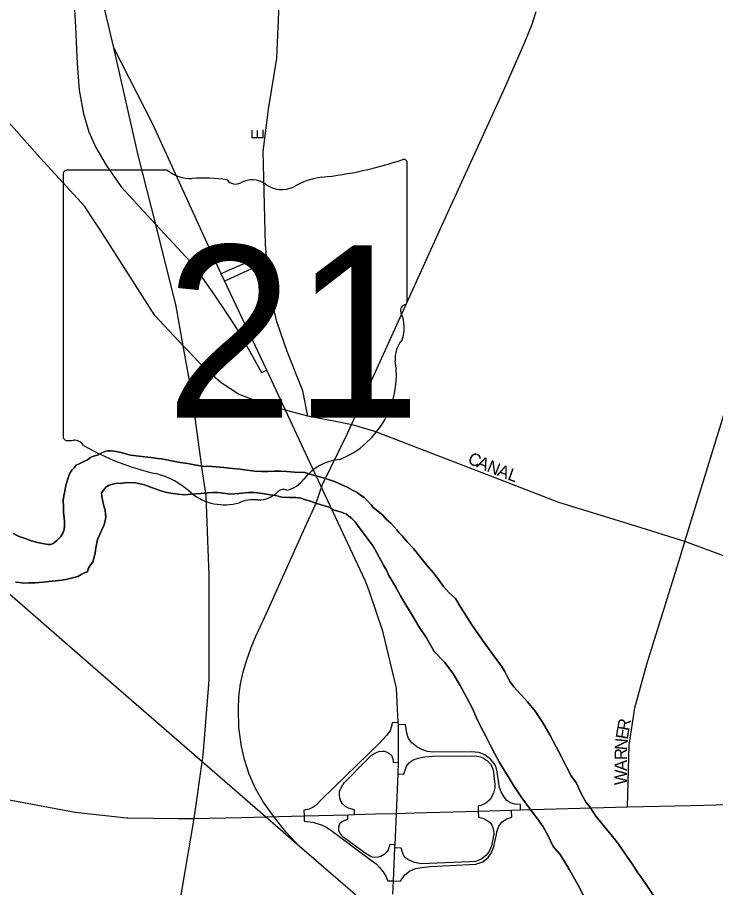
# Model space of a CAD drawing. Extents: x -561 to 1170, y 0 to 846.
# Drawn here: x 278.05 to 285.68, y 204.45 to 213.95 of the extents above; entities that cross this region are included whole.
import ezdxf

# ---------------------------------------------------------------- set-up
doc = ezdxf.new("R2010")
doc.units = 0
for name, color, linetype in [('GM_X_City_Street', 7, 'Continuous'), ('GM_X_City_Street_Text', 7, 'Continuous'), ('GM_X_Interchange_Ramps', 7, 'Continuous'), ('GM_X_Interstate_Route', 7, 'Continuous'), ('GM_X_Major_River', 7, 'Continuous'), ('GM_X_Rail_Line', 7, 'Continuous'), ('GM_X_State_Location', 7, 'Continuous'), ('GM_X_State_Route', 7, 'Continuous'), ('GM_X_State_Shield', 7, 'Continuous')]:
    doc.layers.add(name, color=color, linetype=linetype)

msp = doc.modelspace()

# ---------------------------------------------------------------- linework, layer by layer
at = {"layer": 'GM_X_City_Street'}
for points in [[(280.775, 212.772), (280.7968, 212.9466), (280.8872, 213.5039), (280.9956, 215.9266), (281.0778, 220.8309), (281.1272, 223.8527), (281.2011, 224.3427), (281.5216, 225.8717), (282.3892, 230.0692)], [(285.2926, 208.0563), (285.3457, 208.2277), (286.2713, 211.2389), (286.6055, 212.1521), (286.7989, 212.696), (287.0223, 213.4263), (287.3816, 214.3895), (287.5383, 214.9609), (287.6351, 215.4309), (287.718, 215.9424), (287.739, 216.3547), (287.7421, 216.509), (287.7345, 216.8917), (287.697, 217.6347), (287.5789, 219.1858), (287.5227, 220.4689), (287.5339, 220.8628), (287.5677, 221.1667), (287.6352, 221.5945), (287.8013, 222.1355), (287.8714, 222.4776), (288.0388, 222.7552), (288.458, 223.4643)], [(278.8652, 211.7732), (278.7929, 211.8839), (278.3049, 212.4159), (277.7013, 213.088), (277.4183, 213.3564), (277.0816, 213.5419), (276.7449, 213.6542), (276.4034, 213.6737), (276.0389, 213.6298), (273.3908, 213.1026), (272.0753, 212.8342), (271.6703, 212.7953), (271.385, 212.8644)], [(281.2268, 209.5946), (281.1707, 209.8734), (281.0023, 210.3008), (280.8913, 210.6173), (280.8092, 210.9502), (280.7814, 211.2676), (280.7746, 211.3458), (280.7639, 211.4681), (280.7393, 212.4862), (280.775, 212.772)], [(279.9088, 210.319), (279.8658, 210.3648), (279.5566, 210.6941), (278.9588, 211.6301), (278.8652, 211.7732)], [(281.2268, 209.5946), (280.9846, 209.6601), (280.7791, 209.7158), (280.4679, 209.8364), (280.2806, 209.9604), (280.0964, 210.1192), (279.9088, 210.319)], [(281.6913, 209.5033), (281.5095, 209.5402), (281.2268, 209.5946)], [(283.3187, 208.9034), (281.9589, 209.429), (281.7525, 209.491), (281.6913, 209.5033)], [(284.8106, 208.3926), (283.9695, 208.6518), (283.3187, 208.9034)], [(287.7327, 206.4817), (287.4077, 206.9503), (287.1265, 207.3345), (286.9481, 207.5404), (286.7609, 207.6708), (286.5209, 207.7942), (286.1985, 207.9108), (285.3457, 208.2277), (284.8106, 208.3926)], [(284.7195, 205.3284), (284.7374, 206.002), (284.7973, 206.4096), (284.9311, 206.8879), (285.2926, 208.0563)]]:
    msp.add_lwpolyline(points, dxfattribs=at)
at = {"layer": 'GM_X_Interchange_Ramps'}
for points in [[(278.5779, 215.858), (278.4451, 215.8246), (278.533, 215.3781), (278.584, 215.078), (278.6361, 214.6461), (278.668, 214.2397), (278.6908, 213.8431), (278.7078, 213.4448), (278.7304, 213.1553), (278.775, 212.8977), (278.8333, 212.7007), (278.9097, 212.5278), (279.0235, 212.3347), (279.1876, 212.0997), (279.3923, 211.8767), (279.5649, 211.6893), (279.9399, 211.2825), (280.0643, 211.1176), (280.1829, 210.9511), (280.3521, 210.6987), (280.4557, 210.5403), (280.6092, 210.2769), (280.7208, 210.0705), (280.7807, 210.0967)], [(280.7746, 211.3458), (280.7069, 211.3332), (280.3434, 211.1782), (280.279, 211.1499)], [(280.3158, 211.0728), (280.3771, 211.0996), (280.7157, 211.2554), (280.7814, 211.2676)], [(282.214, 206.2516), (282.149, 206.2476), (282.1415, 206.207), (282.125, 206.1597), (282.0853, 206.1081), (282.0178, 206.0327), (281.3749, 205.4094), (281.3184, 205.3495), (281.2838, 205.3248), (281.2404, 205.3051), (281.1845, 205.2944), (281.1851, 205.232)], [(283.5511, 205.2959), (283.5496, 205.3539), (283.4913, 205.3578), (283.4375, 205.373), (283.4008, 205.4006), (283.375, 205.4333), (283.3393, 205.4928), (283.322, 205.542), (283.3115, 205.5841), (283.3113, 205.587), (283.2951, 205.7134), (283.2888, 205.7441), (283.279, 205.773), (283.2639, 205.8025), (283.2202, 205.854), (283.1634, 205.8941), (283.1263, 205.9121), (283.0933, 205.9215), (283.0139, 205.9295), (282.5913, 205.9286), (282.535, 205.935), (282.4776, 205.9537), (282.4169, 205.9857), (282.3629, 206.0287), (282.3265, 206.0773), (282.3066, 206.1358), (282.2939, 206.2299), (282.2155, 206.2239)], [(281.7371, 205.2463), (281.7361, 205.2983), (281.6726, 205.3142), (281.6374, 205.3339), (281.6051, 205.3618), (281.5883, 205.3929), (281.5774, 205.4253), (281.573, 205.4628), (281.5734, 205.4968), (281.5932, 205.5444), (281.6289, 205.596), (281.8597, 205.8321), (281.9226, 205.8937), (281.9583, 205.9175), (282.0019, 205.9334), (282.0416, 205.9374), (282.0694, 205.9374), (282.1131, 205.9175), (282.1448, 205.8858), (282.1552, 205.8544), (282.1606, 205.8187), (282.2182, 205.815)], [(282.2128, 205.6903), (282.2757, 205.6873), (282.3055, 205.7727), (282.3331, 205.8113), (282.3695, 205.84), (282.4313, 205.8632), (282.5063, 205.8764), (282.5893, 205.8818), (283.0171, 205.8864), (283.0734, 205.8818), (283.1127, 205.875), (283.1458, 205.8618), (283.1893, 205.8321), (283.2224, 205.7949), (283.2351, 205.7716), (283.2458, 205.7422), (283.2532, 205.7095), (283.2639, 205.6318), (283.2703, 205.5782), (283.2697, 205.5362), (283.256, 205.4809), (283.2202, 205.4094), (283.1726, 205.3697), (283.1156, 205.3449), (283.0864, 205.339), (283.0877, 205.283)], [(281.1851, 205.232), (281.1858, 205.1727), (281.2797, 205.1633), (281.3829, 205.1315), (281.4345, 205.1037), (281.494, 205.064), (281.9226, 204.7425), (281.9742, 204.7068), (282.0059, 204.6711), (282.0496, 204.6194), (282.0796, 204.5724), (282.1013, 204.5231), (282.1614, 204.5218)], [(282.179, 204.9144), (282.121, 204.9172), (282.1051, 204.8616), (282.0869, 204.8336), (282.0616, 204.8081), (282.0258, 204.7862), (281.9959, 204.7793), (281.9661, 204.7772), (281.9349, 204.7817), (281.9067, 204.7901), (281.863, 204.818), (281.6131, 205.0005), (281.5852, 205.0323), (281.5654, 205.072), (281.5654, 205.1117), (281.5813, 205.1554), (281.6051, 205.1752), (281.6646, 205.1951), (281.6637, 205.2444)], [(282.1614, 204.5218), (282.24, 204.5202), (282.2877, 204.5877), (282.338, 204.6271), (282.4028, 204.6551), (282.4702, 204.6671), (282.5615, 204.679), (283.0633, 204.7033), (283.1393, 204.7312), (283.1956, 204.7776), (283.2329, 204.8286), (283.2584, 204.8974), (283.2858, 205.0274), (283.2917, 205.0562), (283.314, 205.1197), (283.3306, 205.1452), (283.3512, 205.1672), (283.3991, 205.1982), (283.4544, 205.2189), (283.4526, 205.2931)], [(283.0877, 205.283), (283.0893, 205.2189), (283.1381, 205.205), (283.1965, 205.1752), (283.2172, 205.1579), (283.2361, 205.1315), (283.2488, 205.1021), (283.2555, 205.0673), (283.2569, 205.0376), (283.2545, 205.0126), (283.2322, 204.9053), (283.2083, 204.8418), (283.1726, 204.7981), (283.125, 204.7584), (283.0576, 204.7346), (282.9941, 204.7306), (282.4663, 204.7068), (282.3909, 204.7226), (282.3194, 204.7544), (282.2877, 204.7783), (282.2679, 204.814), (282.248, 204.8775), (282.1775, 204.8809)]]:
    msp.add_lwpolyline(points, dxfattribs=at)
at = {"layer": 'GM_X_Interstate_Route'}
for points in [[(279.6798, 211.2339), (279.5649, 211.6893), (279.3747, 212.4436), (279.1084, 213.615), (278.7106, 215.2972)], [(280.0811, 208.966), (279.9585, 209.8433), (279.8658, 210.3648), (279.7859, 210.8133), (279.6798, 211.2339)], [(279.7274, 203.8659), (279.8229, 204.2383), (279.9855, 205.2009), (280.0818, 205.8926), (280.1475, 206.7146), (280.1475, 207.8572), (280.1147, 208.7253), (280.0811, 208.966)]]:
    msp.add_lwpolyline(points, dxfattribs=at)
at = {"layer": 'GM_X_Major_River'}
for points in [[(284.8807, 204.5395), (284.8255, 204.6202), (284.7758, 204.6954), (284.6211, 204.9211), (284.5715, 204.9855), (284.522, 205.0445), (284.4724, 205.1089), (284.4229, 205.1679), (284.3734, 205.2269), (284.3401, 205.2807), (284.307, 205.329), (284.2685, 205.3773), (284.2352, 205.4365), (284.2019, 205.4957), (284.1627, 205.5873), (284.1021, 205.6679), (284.0575, 205.7594), (284.0019, 205.8671), (283.9408, 205.9856), (283.8687, 206.1147), (283.791, 206.2547), (283.7081, 206.3728), (283.6256, 206.4748), (283.5596, 206.5498), (283.5101, 206.6034), (283.4771, 206.6409), (283.4385, 206.6946), (283.4108, 206.7431), (283.3774, 206.8077), (283.3332, 206.8776), (283.278, 206.9528), (283.2174, 207.0333), (283.1512, 207.1246), (283.0849, 207.2213), (283.0186, 207.318), (282.9577, 207.4148), (282.8969, 207.5062), (282.8415, 207.603), (282.7703, 207.6672), (282.7098, 207.7369), (282.6546, 207.8121), (282.594, 207.8872), (282.5225, 207.973), (282.4509, 208.0642), (282.3794, 208.1501), (282.3133, 208.2251), (282.2584, 208.2895), (282.2199, 208.3269), (282.1979, 208.3537), (282.1649, 208.3913), (282.132, 208.4288), (282.0827, 208.4715), (282.0441, 208.5198), (281.9402, 208.5998), (281.9181, 208.6267), (281.8797, 208.6696), (281.8413, 208.707), (281.803, 208.7336), (281.7648, 208.7603), (281.7157, 208.7868), (281.6557, 208.8185), (281.5903, 208.8503), (281.5195, 208.8819), (281.4434, 208.9081), (281.3564, 208.9341), (281.2749, 208.9548), (281.1934, 208.9809), (281.0797, 208.9849), (280.9984, 208.9894), (280.928, 208.994), (280.8576, 208.9931), (280.7927, 208.9923), (280.7223, 208.9915), (280.6465, 208.996), (280.5652, 209.0058), (280.4893, 209.0158), (280.4025, 209.0256), (280.3104, 209.0353), (280.1803, 209.0445), (280.0774, 209.0487), (279.9906, 209.0639), (279.9146, 209.0793), (279.8333, 209.0891), (279.7573, 209.1044), (279.6867, 209.1198), (279.6271, 209.13), (279.5837, 209.1349), (279.5403, 209.1397), (279.2909, 209.1692), (279.2148, 209.19), (279.1388, 209.2107), (279.0792, 209.2154), (279.0413, 209.215), (279.0089, 209.2092), (278.9605, 209.1869), (278.9283, 209.1703), (278.8851, 209.1589), (278.8529, 209.1423), (278.8207, 209.1202), (278.7723, 209.098), (278.7293, 209.0758)], [(278.7293, 209.0758), (278.7723, 209.098), (278.8207, 209.1202), (278.8529, 209.1423), (278.8851, 209.1589), (278.9283, 209.1703), (278.9605, 209.1869), (279.0089, 209.2092), (279.0413, 209.215), (279.0792, 209.2154), (279.1388, 209.2107), (279.2148, 209.19), (279.2909, 209.1692), (279.5403, 209.1397), (279.5837, 209.1349), (279.6271, 209.13), (279.6867, 209.1198), (279.7573, 209.1044), (279.8333, 209.0891), (279.9146, 209.0793), (279.9906, 209.0639), (280.0774, 209.0487), (280.1803, 209.0445), (280.3104, 209.0353), (280.4025, 209.0256), (280.4893, 209.0158), (280.5652, 209.0058), (280.6465, 208.996), (280.7223, 208.9915), (280.7927, 208.9923), (280.8576, 208.9931), (280.928, 208.994), (280.9984, 208.9894), (281.0797, 208.9849), (281.1934, 208.9809), (281.2749, 208.9548), (281.3564, 208.9341), (281.4434, 208.9081), (281.5195, 208.8819), (281.5903, 208.8503), (281.6557, 208.8185), (281.7157, 208.7868), (281.7648, 208.7603), (281.803, 208.7336), (281.8413, 208.707), (281.8797, 208.6696), (281.9181, 208.6267), (281.9402, 208.5998), (282.0441, 208.5198), (282.0827, 208.4715), (282.132, 208.4288), (282.1649, 208.3913), (282.1979, 208.3537), (282.2199, 208.3269), (282.2584, 208.2895), (282.3133, 208.2251), (282.3794, 208.1501), (282.4509, 208.0642), (282.5225, 207.973), (282.594, 207.8872), (282.6546, 207.8121), (282.7098, 207.7369), (282.7703, 207.6672), (282.8415, 207.603), (282.8969, 207.5062), (282.9577, 207.4148), (283.0186, 207.318), (283.0849, 207.2213), (283.1512, 207.1246), (283.2174, 207.0333), (283.278, 206.9528), (283.3332, 206.8776), (283.3774, 206.8077), (283.4108, 206.7431), (283.4385, 206.6946), (283.4771, 206.6409), (283.5101, 206.6034), (283.5596, 206.5498), (283.6256, 206.4748), (283.7081, 206.3728), (283.791, 206.2547), (283.8687, 206.1147), (283.9408, 205.9856), (284.0019, 205.8671), (284.0575, 205.7594), (284.1021, 205.6679), (284.1627, 205.5873), (284.2019, 205.4957), (284.2352, 205.4365), (284.2685, 205.3773), (284.307, 205.329), (284.3401, 205.2807), (284.3734, 205.2269), (284.4229, 205.1679), (284.4724, 205.1089), (284.522, 205.0445), (284.5715, 204.9855), (284.6211, 204.9211), (284.7758, 204.6954), (284.8255, 204.6202), (284.8807, 204.5395)], [(278.7293, 209.0758), (278.697, 209.0591), (278.6757, 209.0318), (278.6491, 209.0044), (278.6279, 208.9716), (278.6122, 208.9335), (278.6018, 208.9009), (278.5914, 208.8629), (278.5812, 208.8194), (278.571, 208.7759), (278.5609, 208.727), (278.5562, 208.6728), (278.557, 208.6078), (278.558, 208.5428), (278.5641, 208.4887), (278.5702, 208.44), (278.5708, 208.3967), (278.5659, 208.3587), (278.5555, 208.326), (278.529, 208.2824), (278.481, 208.233), (278.4435, 208.2055), (278.4166, 208.1943), (278.3895, 208.194), (278.3298, 208.2041), (278.2756, 208.2143), (278.2103, 208.2352), (278.1396, 208.2614), (278.0744, 208.2823), (278.009, 208.314)], [(278.009, 208.314), (278.0744, 208.2823), (278.1396, 208.2614), (278.2103, 208.2352), (278.2756, 208.2143), (278.3298, 208.2041), (278.3895, 208.194), (278.4166, 208.1943), (278.4435, 208.2055), (278.481, 208.233), (278.529, 208.2824), (278.5555, 208.326), (278.5659, 208.3587), (278.5708, 208.3967), (278.5702, 208.44), (278.5641, 208.4887), (278.558, 208.5428), (278.557, 208.6078), (278.5562, 208.6728), (278.5609, 208.727), (278.571, 208.7759), (278.5812, 208.8194), (278.5914, 208.8629), (278.6018, 208.9009), (278.6122, 208.9335), (278.6279, 208.9716), (278.6491, 209.0044), (278.6757, 209.0318), (278.697, 209.0591), (278.7293, 209.0758)], [(279.0187, 208.4942), (279.0183, 208.5266), (279.0123, 208.5699), (279.001, 208.6023), (278.9952, 208.6293), (278.9836, 208.6834), (278.9777, 208.7212), (278.9718, 208.7591), (278.9984, 208.7919), (279.0197, 208.8192), (279.0573, 208.8414), (279.095, 208.8526), (279.1436, 208.8641), (279.1815, 208.8591), (279.2463, 208.8707), (279.3438, 208.8665), (279.4415, 208.846), (279.5285, 208.8145), (279.6102, 208.783), (279.6862, 208.7623), (279.7513, 208.7522), (279.811, 208.7421), (279.8814, 208.7375), (279.9517, 208.7438), (280.0599, 208.7505), (280.1301, 208.7568), (280.1896, 208.7629), (280.2437, 208.7636), (280.3034, 208.7535), (280.3847, 208.7436), (280.4766, 208.7501), (280.5739, 208.7621), (280.6443, 208.763), (280.704, 208.7529), (280.7527, 208.7481), (280.8178, 208.738), (280.8721, 208.7278), (280.9427, 208.7124), (281.0239, 208.708), (281.0943, 208.7088), (281.1539, 208.6987), (281.2029, 208.6831), (281.2572, 208.6675), (281.3116, 208.6464), (281.3714, 208.6255), (281.4475, 208.6048), (281.513, 208.5676), (281.5836, 208.5522), (281.6217, 208.5364), (281.6489, 208.5259), (281.6762, 208.5046), (281.7091, 208.4779), (281.7421, 208.4404), (281.7862, 208.3813), (281.9405, 208.1773), (281.9795, 208.1019), (282.0294, 208.0158), (282.0571, 207.962), (282.0849, 207.9135), (282.1128, 207.8543), (282.1515, 207.7898), (282.1904, 207.7198), (282.2403, 207.6337), (282.2957, 207.5369), (282.3676, 207.4239), (282.4397, 207.3002), (282.5226, 207.1766), (282.6058, 207.0259), (282.7211, 206.9081), (282.8093, 206.79), (282.8924, 206.6555), (282.9646, 206.521), (283.0257, 206.4025), (283.0704, 206.3001), (283.1206, 206.1978), (283.1706, 206.1009), (283.2207, 205.9986), (283.2707, 205.9071), (283.3151, 205.8209), (283.3706, 205.7295), (283.4148, 205.6596), (283.448, 205.6058), (283.4812, 205.552), (283.5199, 205.4929), (283.5641, 205.4284), (283.6138, 205.3586), (283.6744, 205.2781), (283.7351, 205.1975), (283.7958, 205.1116), (283.8512, 205.0147), (283.907, 204.8962), (283.9839, 204.8104), (284.0338, 204.7244), (284.0836, 204.6437), (284.1335, 204.5576), (284.1835, 204.4661), (284.239, 204.3638)], [(284.239, 204.3638), (284.1835, 204.4661), (284.1335, 204.5576), (284.0836, 204.6437), (284.0338, 204.7244), (283.9839, 204.8104), (283.907, 204.8962), (283.8512, 205.0147), (283.7958, 205.1116), (283.7351, 205.1975), (283.6744, 205.2781), (283.6138, 205.3586), (283.5641, 205.4284), (283.5199, 205.4929), (283.4812, 205.552), (283.448, 205.6058), (283.4148, 205.6596), (283.3706, 205.7295), (283.3151, 205.8209), (283.2707, 205.9071), (283.2207, 205.9986), (283.1706, 206.1009), (283.1206, 206.1978), (283.0704, 206.3001), (283.0257, 206.4025), (282.9646, 206.521), (282.8924, 206.6555), (282.8093, 206.79), (282.7211, 206.9081), (282.6058, 207.0259), (282.5226, 207.1766), (282.4397, 207.3002), (282.3676, 207.4239), (282.2957, 207.5369), (282.2403, 207.6337), (282.1904, 207.7198), (282.1515, 207.7898), (282.1128, 207.8543), (282.0849, 207.9135), (282.0571, 207.962), (282.0294, 208.0158), (281.9795, 208.1019), (281.9405, 208.1773), (281.7862, 208.3813), (281.7421, 208.4404), (281.7091, 208.4779), (281.6762, 208.5046), (281.6489, 208.5259), (281.6217, 208.5364), (281.5836, 208.5522), (281.513, 208.5676), (281.4475, 208.6048), (281.3714, 208.6255), (281.3116, 208.6464), (281.2572, 208.6675), (281.2029, 208.6831), (281.1539, 208.6987), (281.0943, 208.7088), (281.0239, 208.708), (280.9427, 208.7124), (280.8721, 208.7278), (280.8178, 208.738), (280.7527, 208.7481), (280.704, 208.7529), (280.6443, 208.763), (280.5739, 208.7621), (280.4766, 208.7501), (280.3847, 208.7436), (280.3034, 208.7535), (280.2437, 208.7636), (280.1896, 208.7629), (280.1301, 208.7568), (280.0599, 208.7505), (279.9517, 208.7438), (279.8814, 208.7375), (279.811, 208.7421), (279.7513, 208.7522), (279.6862, 208.7623), (279.6102, 208.783), (279.5285, 208.8145), (279.4415, 208.846), (279.3438, 208.8665), (279.2463, 208.8707), (279.1815, 208.8591), (279.1436, 208.8641), (279.095, 208.8526), (279.0573, 208.8414), (279.0197, 208.8192), (278.9984, 208.7919), (278.9718, 208.7591), (278.9777, 208.7212), (278.9836, 208.6834), (278.9952, 208.6293), (279.001, 208.6023), (279.0123, 208.5699), (279.0183, 208.5266), (279.0187, 208.4942)], [(278.0325, 207.7834), (278.0759, 207.7785), (278.1246, 207.7736), (278.1842, 207.7744), (278.2491, 207.7752), (278.3356, 207.7816), (278.4329, 207.7936), (278.5086, 207.8), (278.541, 207.8057), (278.5842, 207.8117), (278.6274, 207.8231), (278.6705, 207.8344), (278.7136, 207.8458), (278.7512, 207.8679), (278.7942, 207.8901), (278.8212, 207.8958), (278.8262, 207.9284), (278.8526, 207.972), (278.8793, 207.9995), (278.8896, 208.0429), (278.905, 208.1027), (278.9097, 208.157), (278.9301, 208.2493), (278.972, 208.3473), (279.0037, 208.4073), (279.0138, 208.4562), (279.0187, 208.4942)], [(279.0187, 208.4942), (279.0138, 208.4562), (279.0037, 208.4073), (278.972, 208.3473), (278.9301, 208.2493), (278.9097, 208.157), (278.905, 208.1027), (278.8896, 208.0429), (278.8793, 207.9995), (278.8526, 207.972), (278.8262, 207.9284), (278.8212, 207.8958), (278.7942, 207.8901), (278.7512, 207.8679), (278.7136, 207.8458), (278.6705, 207.8344), (278.6274, 207.8231), (278.5842, 207.8117), (278.541, 207.8057), (278.5086, 207.8), (278.4329, 207.7936), (278.3356, 207.7816), (278.2491, 207.7752), (278.1842, 207.7744), (278.1246, 207.7736), (278.0759, 207.7785), (278.0325, 207.7834)], [(285.7138, 203.3902), (285.664, 203.4709), (285.6032, 203.5622), (285.537, 203.6535), (285.4707, 203.7502), (285.4044, 203.847), (285.3378, 203.9708), (285.2554, 204.0565), (285.1948, 204.137), (285.1288, 204.2121), (285.0628, 204.2871), (284.9967, 204.373), (284.936, 204.459), (284.8807, 204.5395)], [(284.8807, 204.5395), (284.936, 204.459), (284.9967, 204.373), (285.0628, 204.2871), (285.1288, 204.2121), (285.1948, 204.137), (285.2554, 204.0565), (285.3378, 203.9708), (285.4044, 203.847), (285.4707, 203.7502), (285.537, 203.6535), (285.6032, 203.5622), (285.664, 203.4709), (285.7138, 203.3902)]]:
    msp.add_lwpolyline(points, dxfattribs=at)
at = {"layer": 'GM_X_Rail_Line'}
for points in [[(281.132, 204.9023), (280.9283, 205.0781), (278.8808, 206.8539), (276.7072, 208.7486), (276.098, 209.1948), (275.5867, 209.5104), (274.7817, 209.7606), (273.9223, 209.9565), (269.7124, 210.1959), (268.6789, 210.3047), (268.0045, 210.468), (267.3626, 210.7291), (266.6991, 211.0991), (266.0899, 211.5779), (265.5677, 212.1655), (264.9585, 213.0143), (262.048, 216.9812)], [(281.132, 204.9023), (280.9882, 205.0562), (280.8623, 205.214), (280.7405, 205.3858), (280.6546, 205.5316), (280.5877, 205.6864), (280.5357, 205.8452), (280.5038, 205.989), (280.4748, 206.1948), (280.4708, 206.3945), (280.4748, 206.5333), (280.4918, 206.6722), (280.5158, 206.788), (280.5557, 206.9229), (280.6086, 207.0697), (280.6606, 207.1945), (280.7774, 207.4522), (281.1939, 208.3761), (281.3128, 208.6377), (281.3887, 208.8505), (281.6564, 209.3988), (282.3085, 210.834), (282.6971, 211.69), (283.3802, 213.1811), (283.596, 213.6785), (283.6759, 213.8763), (283.7218, 214.0121)], [(285.7723, 200.6356), (285.6784, 200.7475), (285.5306, 200.9272), (285.3668, 201.113), (285.155, 201.3447), (285.0032, 201.5005), (284.8614, 201.6424), (284.7096, 201.7902), (284.5498, 201.94), (284.348, 202.1198), (283.0456, 203.2484), (281.132, 204.9023)]]:
    msp.add_lwpolyline(points, dxfattribs=at)
at = {"layer": 'GM_X_State_Route'}
for points in [[(280.279, 211.1499), (279.5353, 212.7844), (279.1084, 213.615)], [(281.2322, 209.1301), (280.9846, 209.6601), (280.7807, 210.0967), (280.3158, 211.0728), (280.279, 211.1499)], [(281.853, 207.8011), (281.2322, 209.1301)], [(281.8992, 207.6761), (281.8652, 207.7751), (281.853, 207.8011)], [(282.1549, 204.3764), (282.1614, 204.5218), (282.1775, 204.8809), (282.179, 204.9144), (282.1944, 205.2581), (282.2128, 205.6903), (282.2182, 205.815), (282.2155, 206.2239), (282.214, 206.2516), (282.1939, 206.6242), (282.046, 207.2489), (281.8992, 207.6761)], [(272.4661, 206.1585), (272.7094, 206.1535), (273.2285, 206.14), (273.78, 206.1212), (274.2235, 206.0857), (274.5914, 206.0388), (275.1272, 205.9388), (278.6873, 205.2713), (279.2477, 205.2085), (279.2607, 205.2084)], [(285.4132, 205.3461), (288.4193, 205.4229), (288.4213, 205.423)], [(282.3929, 205.2637), (283.0877, 205.283), (283.4526, 205.2931), (283.5511, 205.2959), (284.7195, 205.3284), (285.4132, 205.3461)], [(279.8106, 205.2027), (279.9855, 205.2009), (280.4979, 205.2142)], [(280.4979, 205.2142), (281.1851, 205.232), (281.6637, 205.2444), (281.7371, 205.2463), (281.9657, 205.2522)], [(281.9657, 205.2522), (282.1944, 205.2581), (282.3929, 205.2637)], [(279.2607, 205.2084), (279.8106, 205.2027)]]:
    msp.add_lwpolyline(points, dxfattribs=at)
at = {"layer": 'GM_X_State_Shield'}
for p, q in [((282.3131, 210.8583), (282.3131, 212.3507)), ((279.6921, 212.28), (278.5913, 212.28)), ((278.5543, 212.2309), (278.5543, 209.378)), ((282.3128, 210.8587), (282.3131, 210.8583))]:
    msp.add_line(p, q, dxfattribs=at)
for centre, radius, start, end in [((280.9742, 216.1695), 3.9862, 275.84447, 288.90645), ((282.2714, 212.3569), 0.0418, 351.86209, 97.738), ((278.5973, 212.237), 0.0435, 98.1301, 188.1301), ((279.9542, 212.6112), 0.4224, 231.61951, 271.11188), ((280.0943, 210.6784), 1.5163, 80.48669, 94.98827), ((280.4385, 212.2518), 0.1219, 219.79206, 297.10237), ((280.6174, 211.9221), 0.2533, 54.46668, 119.14113), ((281.4826, 211.4087), 0.802, 97.34618, 120.76885), ((280.9444, 212.3743), 0.3048, 233.85621, 294.82819), ((282.2685, 210.8526), 0.0448, 289.60381, 7.73413), ((282.3035, 210.7488), 0.0648, 107.94398, 210.33697), ((281.8915, 210.5601), 0.3887, 340.03296, 23.64957), ((282.463, 210.2338), 0.2828, 136.8065, 186.92959), ((281.1975, 210.0439), 0.997, 292.30889, 8.98584), ((278.5977, 209.3718), 0.0439, 171.95839, 258.30661), ((278.6044, 209.6637), 0.3353, 267.33899, 280.60386), ((278.673, 209.2134), 0.1209, 29.74838, 93.27175), ((280.1992, 211.7767), 2.8786, 240.41292, 257.1985), ((281.6179, 208.5771), 0.5461, 94.40312, 142.57675), ((279.341, 208.0963), 0.9007, 47.18416, 75.83597), ((280.926, 209.1015), 0.3221, 282.87319, 323.27711), ((280.3151, 209.1993), 0.5715, 230.70037, 286.29184), ((280.6871, 208.9856), 0.3045, 268.77702, 315.54927), ((280.9626, 208.7093), 0.0857, 65.75173, 132.64842), ((280.6454, 208.2129), 0.4696, 85.69512, 111.20995)]:
    msp.add_arc(centre, radius, start, end, dxfattribs=at)

# ---------------------------------------------------------------- texts
at = {"layer": 'GM_X_City_Street_Text'}
for s, rotation, p in [('E', 90, (280.7434, 212.6121)), ('C', 337.28299, (282.9645, 209.0834)), ('A', 337.28445, (283.0631, 209.0421)), ('N', 337.28445, (283.1727, 208.9963)), ('A', 338.96552, (283.2863, 208.9489)), ('L', 340.29931, (283.4004, 208.905)), ('R', 80.13834, (284.7364, 206.1535)), ('E', 80.47478, (284.7207, 206.06)), ('N', 85.47052, (284.7117, 205.9446)), ('R', 89.91069, (284.7117, 205.8405)), ('A', 89.91255, (284.7115, 205.7217)), ('W', 89.91593, (284.7113, 205.5673))]:
    msp.add_text(s, height=0.135, rotation=rotation, dxfattribs=at).set_placement(p)
at = {"layer": 'GM_X_State_Location'}
for s in ['s', 'r']:
    msp.add_text(s, height=0.0027, dxfattribs=at).set_placement((280.3913, 210.6148))
msp.add_text('21', height=0.0027, rotation=0.00001, dxfattribs=at).set_placement((279.7115, 210.4184))
at = {"layer": 'GM_X_State_Shield'}
msp.add_text('21', height=1.87946, dxfattribs=at).set_placement((279.6716, 209.5792))

doc.saveas('drawing.dxf')
